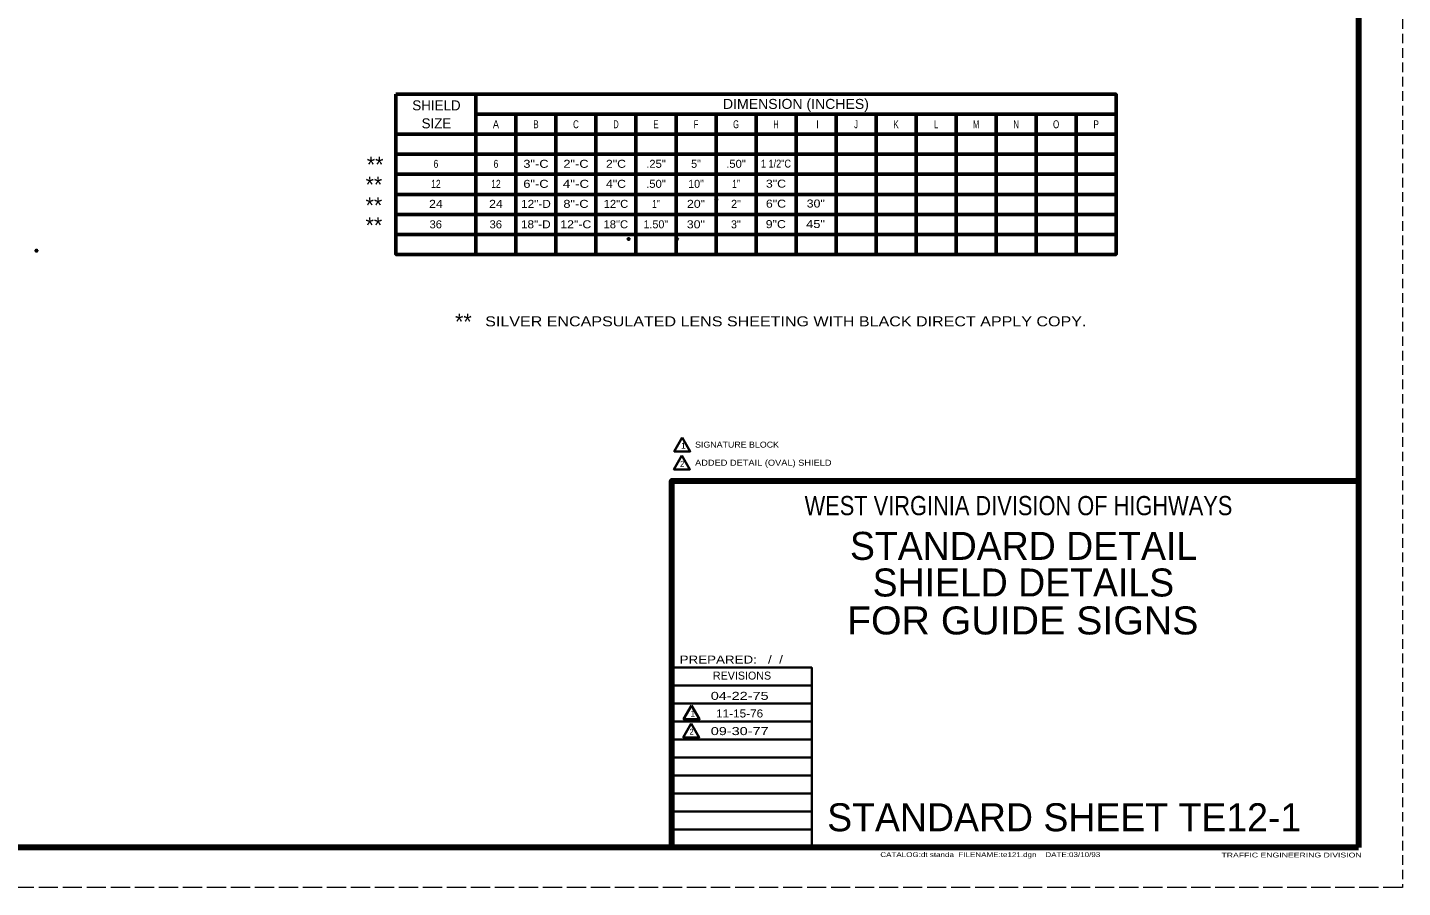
# Model space of a CAD drawing. Extents: x -55 to 625, y -354 to 86.
# Drawn here: x 281.5 to 625.2, y -353.6 to -138.9 of the extents above; entities that cross this region are included whole.
import ezdxf
from ezdxf.enums import TextEntityAlignment as Align

# ---------------------------------------------------------------- set-up
doc = ezdxf.new("R2010")
doc.units = 0
doc.header["$LTSCALE"] = 0.8
doc.header["$PDMODE"] = 32
doc.header["$PDSIZE"] = 0.4
doc.linetypes.add('LONG_DASHED', pattern=[7.5, 6, -1.5])
doc.linetypes.add('MEDIUM_DASHED', pattern=[4.5, 3, -1.5])
doc.layers.add('1', color=7, linetype='Continuous', lineweight=40)
doc.layers.add('61', color=7, linetype='Continuous', lineweight=35)

msp = doc.modelspace()

# ---------------------------------------------------------------- linework, layer by layer
at = {"layer": '1', "linetype": 'MEDIUM_DASHED', "lineweight": 13}
msp.add_line((625.1827, 86.3965), (625.1627, -353.6235), dxfattribs=at)
at = {"layer": '1', "lineweight": 53}
for p, q in [((393.6178, -195.529), (393.6178, -155.529)), ((393.6178, -160.529), (553.6178, -160.529)), ((403.6178, -195.529), (403.6178, -160.529)), ((413.6178, -195.529), (413.6178, -160.529)), ((423.6178, -195.529), (423.6178, -160.529)), ((433.6178, -195.529), (433.6178, -160.529)), ((443.6178, -195.529), (443.6178, -160.529)), ((453.6178, -195.529), (453.6178, -160.529)), ((463.6178, -195.529), (463.6178, -160.529)), ((473.6178, -195.529), (473.6178, -160.529)), ((483.6178, -195.529), (483.6178, -160.529)), ((493.6178, -195.529), (493.6178, -160.529)), ((503.6178, -195.529), (503.6178, -160.529)), ((513.6178, -195.529), (513.6178, -160.529)), ((523.6178, -195.529), (523.6178, -160.529)), ((533.6178, -195.529), (533.6178, -160.529)), ((543.6178, -195.529), (543.6178, -160.529)), ((473.6178, -165.529), (483.6178, -165.529)), ((481.1178, -165.529), (496.1178, -165.529)), ((373.6178, -170.529), (553.6178, -170.529)), ((373.6178, -175.529), (553.6178, -175.529)), ((373.6178, -180.529), (553.6178, -180.529)), ((373.6178, -185.529), (553.6178, -185.529)), ((373.6178, -190.529), (553.6178, -190.529))]:
    msp.add_line(p, q, dxfattribs=at)
at = {"layer": '1', "lineweight": 35}
for p, q in [((477.5627, -303.2035), (442.5827, -303.2035)), ((477.5627, -307.7035), (442.5827, -307.7035)), ((477.5627, -312.2035), (442.5827, -312.2035)), ((477.5627, -316.7235), (442.5827, -316.7235)), ((477.5627, -321.2035), (442.5827, -321.2035)), ((477.5627, -325.6835), (442.5827, -325.6835)), ((477.5627, -330.1835), (442.5827, -330.1835)), ((477.5627, -334.6835), (442.5827, -334.6835)), ((477.5627, -339.2035), (442.5827, -339.2035))]:
    msp.add_line(p, q, dxfattribs=at)
at = {"layer": '1', "lineweight": 53}
msp.add_lwpolyline([(373.6178, -155.529), (553.6178, -155.529), (553.6178, -195.529), (373.6178, -195.529)], close=True, dxfattribs=at)
for points in [[(373.6178, -165.529), (393.6178, -165.529), (403.6178, -165.529), (413.6178, -165.529), (423.6178, -165.529), (433.6178, -165.529), (443.6178, -165.529), (453.6178, -165.529), (463.6178, -165.529), (476.1178, -165.529)], [(493.6178, -165.529), (503.6178, -165.529), (513.6178, -165.529), (523.6178, -165.529), (533.6178, -165.529), (543.6178, -165.529), (553.6178, -165.529)]]:
    msp.add_lwpolyline(points, dxfattribs=at)
at = {"layer": '1', "lineweight": 35}
for points in [[(445.1797, -241.2684), (443.1797, -244.7325), (447.1797, -244.7325)], [(445.1049, -245.7766), (443.1049, -249.2407), (447.1049, -249.2407)], [(447.5216, -308.1804), (445.5216, -311.6445), (449.5216, -311.6445)], [(447.4468, -312.6886), (445.4468, -316.1527), (449.4468, -316.1527)]]:
    msp.add_lwpolyline(points, close=True, dxfattribs=at)
at = {"layer": '1', "lineweight": 158}
msp.add_lwpolyline([(442.5627, -343.6435), (442.5627, -252.0635), (614.2227, -252.0635)], dxfattribs=at)
at = {"layer": '1', "lineweight": 35}
msp.add_lwpolyline([(477.5627, -343.6835), (477.5627, -298.7235), (442.5827, -298.7235)], dxfattribs=at)
at = {"layer": '1'}
for p in [(453.6962, -181.8756), (431.7653, -191.7061), (443.8657, -191.7061), (283.793, -194.6168)]:
    msp.add_point(p, dxfattribs=at)
at = {"layer": '61', "lineweight": 158}
for p, q in [((614.2027, 76.3965), (614.2227, -343.6435)), ((614.2227, -343.6435), (-24.8373, -343.6235))]:
    msp.add_line(p, q, dxfattribs=at)
at = {"layer": '61', "linetype": 'LONG_DASHED', "lineweight": 13}
msp.add_line((625.1627, -353.6235), (-54.8973, -353.6435), dxfattribs=at)

# ---------------------------------------------------------------- texts
at = {"layer": '1'}
for s, height, p in [('SHIELD', 2.5, (383.7511, -159.5565)), ('SIZE', 2.5, (383.7511, -164.0565)), ('I', 2, (478.986, -164.029)), ('**', 4, (368.4289, -175.093)), ('5"', 2, (448.6178, -173.9066)), ('**', 4, (368.1235, -180.0906)), ('10"', 2, (448.6178, -178.9066)), ('**', 4, (368.1235, -185.2577)), ('2"', 2, (458.6178, -183.9066)), ('**', 4, (368.1235, -190.2402)), ('1.50"', 2, (438.5773, -189.0143)), ('3"', 2, (458.5773, -189.0143)), ('**', 4, (390.4756, -214.3203)), ('STANDARD DETAIL', 6.993, (530.4796, -271.8235)), ('SHIELD DETAILS', 6.993, (530.433, -280.9696))]:
    msp.add_text(s, height=height, dxfattribs=at).set_placement(p, align=Align.CENTER)
for s, height, width, p in [('DIMENSION (INCHES)', 2.5, 1.05, (473.588, -159.197)), ('A', 2, 0.85, (398.6178, -164.029)), ('B', 2, 0.75, (408.6178, -164.029)), ('C', 2, 0.75, (418.6177, -164.029)), ('D', 2, 0.7, (428.6178, -164.029)), ('E', 2, 0.7, (438.6178, -164.029)), ('F', 2, 0.75, (448.6178, -164.029)), ('G', 2, 0.7, (458.6177, -164.029)), ('H', 2, 0.7, (468.6178, -164.029)), ('J', 2, 0.7, (488.6178, -164.029)), ('K', 2, 0.75, (498.6178, -164.029)), ('L', 2, 0.75, (508.6178, -164.029)), ('M', 2, 0.7, (518.6177, -164.029)), ('N', 2, 0.7, (528.6178, -164.029)), ('O', 2, 0.75, (538.6177, -164.029)), ('P', 2, 0.75, (548.6178, -164.029)), ('1 1/2"C', 2, 0.85, (468.6011, -173.8607)), ('6', 2, 0.8, (383.6178, -173.9066)), ('6', 2, 0.8, (398.6178, -173.9066)), ('3"-C', 2, 1.2, (408.6177, -173.9066)), ('2"-C', 2, 1.2, (418.6178, -173.9066)), ('2"C', 2, 1.15, (428.6178, -173.9066)), ('.25"', 2, 1.05, (438.6178, -173.9066)), ('.50"', 2, 1.05, (458.6178, -173.9066)), ('12', 2, 0.8, (383.6178, -178.9066)), ('12', 2, 0.8, (398.6177, -178.9066)), ('6"-C', 2, 1.2, (408.6178, -178.9066)), ('4"-C', 2, 1.25, (418.6178, -178.9066)), ('4"C', 2, 1.15, (428.6179, -178.9066)), ('.50"', 2, 1.05, (438.6178, -178.9066)), ('1"', 2, 0.8, (458.6178, -178.9066)), ('3"C', 2, 1.15, (468.6011, -178.8607)), ('24', 2, 1.15, (383.6178, -183.9066)), ('24', 2, 1.15, (398.6178, -183.9066)), ('12"-D', 2, 1.1, (408.6177, -183.9066)), ('8"-C', 2, 1.2, (418.6178, -183.9066)), ('12"C', 2, 1.05, (428.6178, -183.9066)), ('1"', 2, 0.8, (438.6178, -183.9066)), ('20"', 2, 1.15, (448.6178, -183.9066)), ('6"C', 2, 1.15, (468.601, -183.8607)), ('30"', 2, 1.15, (478.5424, -183.825)), ('36', 2, 1.05, (383.5773, -189.0143)), ('36', 2, 1.05, (398.5773, -189.0143)), ('18"-D', 2, 1.1, (408.5772, -189.0143)), ('12"-C', 2, 1.15, (418.5772, -189.0143)), ('18"C', 2, 1.05, (428.5773, -189.0143)), ('30"', 2, 1.15, (448.5773, -189.0143)), ('9"C', 2, 1.15, (468.5605, -188.9683)), ('45"', 2, 1.2, (478.5019, -188.9327)), ('WEST VIRGINIA DIVISION OF HIGHWAYS', 4.795, 0.85, (529.211, -260.6635)), ('FOR GUIDE SIGNS', 6.993, 1.05, (530.2667, -290.4482)), ('04-22-75', 2, 1.35, (459.5319, -306.7835)), ('11-15-76', 2, 1.1, (459.5119, -311.1835)), ('09-30-77', 2, 1.35, (459.5319, -315.5835))]:
    msp.add_text(s, height=height, dxfattribs=dict(at, width=width)).set_placement(p, align=Align.CENTER)
for s, height, width, p in [('SILVER ENCAPSULATED LENS SHEETING WITH BLACK DIRECT APPLY COPY.', 2.5, 1.2, (395.9292, -213.4968)), ('SIGNATURE BLOCK', 1.5, 1.1, (448.3886, -243.7872)), ('2', 1.5, 0.9, (444.6425, -248.6005)), ('ADDED DETAIL (OVAL) SHIELD', 1.5, 1.15, (448.3886, -248.3071)), ('PREPARED:   /  /  ', 1.998, 1.25, (444.5227, -297.7235)), ('2', 1.5, 0.9, (446.9844, -315.5125)), ('CATALOG:dt standa  FILENAME:te121.dgn    DATE:03/10/93', 1.2, 1.25, (494.6827, -346.0435)), ('TRAFFIC ENGINEERING DIVISION', 1.2, 1.35, (579.9427, -346.1435))]:
    msp.add_text(s, height=height, dxfattribs=dict(at, width=width)).set_placement(p)
for s, height, p in [('1', 1.5, (444.8987, -244.0433)), ('REVISIONS', 1.998, (452.8427, -301.7235)), ('1', 1.5, (447.2406, -310.9553)), ('STANDARD SHEET TE12-1', 6.993, (481.4027, -339.6035))]:
    msp.add_text(s, height=height, dxfattribs=at).set_placement(p)

doc.saveas('drawing.dxf')
